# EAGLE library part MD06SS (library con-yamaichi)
YAMAICHI CONNECTOR
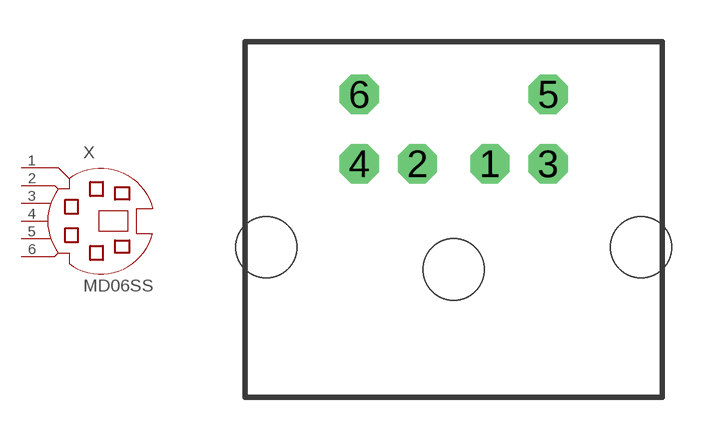
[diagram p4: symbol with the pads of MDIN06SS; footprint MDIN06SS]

Designator prefix X

## MD06SS (OC_FARNELL: unknown; OC_NEWARK: unknown)  [MDIN06SS]
1  1  pas
2  2  pas
3  3  pas
4  4  pas
5  5  pas
6  6  pas

## Footprint MDIN06SS (pad centres in mm)
Mini Din YAMAICHI CONNECTOR
drill 0.9 octagon: 1 1.3,8.5; 2 -1.3,8.5; 3 3.4,8.5; 4 -3.4,8.5; 5 3.4,11; 6 -3.4,11
hole 2.2 at -6.75,5.5
hole 2.2 at 0,4.7
hole 2.2 at 6.75,5.5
